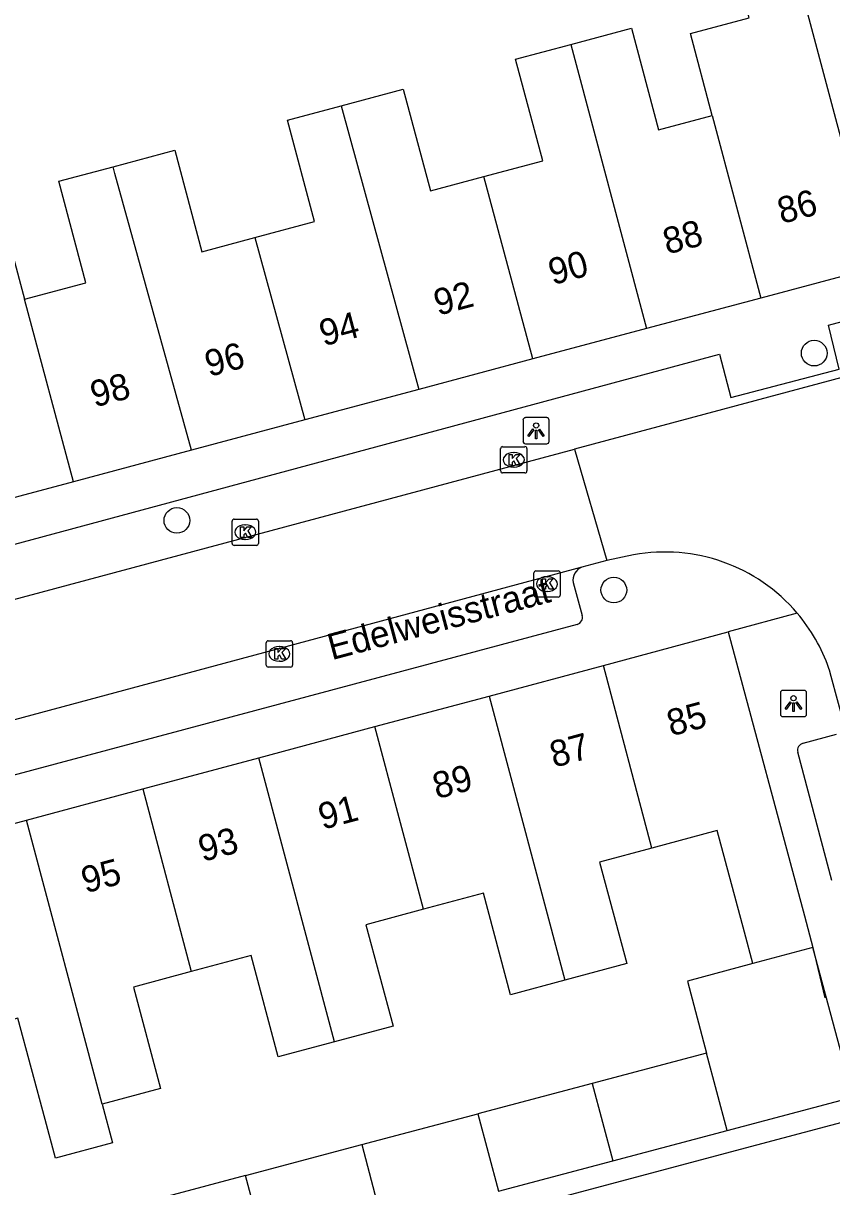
# Model space of a CAD drawing. Extents: x 162542 to 163144, y 380786 to 381511.
# Drawn here: x 162830.58 to 162861.37, y 381053.03 to 381097.35 of the extents above; entities that cross this region are included whole.
import ezdxf

# ---------------------------------------------------------------- set-up
doc = ezdxf.new("R2010")
doc.units = 0
for name, color, linetype in [('IMGEO_Boom', 7, 'Continuous'), ('IMGEO_Kolk', 7, 'Continuous'), ('IMGEO_Lichtpunt', 7, 'Continuous'), ('IMGEO_Muur', 7, 'Continuous'), ('IMGEO_Openbare_ruimte_label', 7, 'Continuous'), ('IMGEO_Pand', 7, 'Continuous'), ('IMGEO_Pand_nummerreeks', 7, 'Continuous'), ('IMGEO_Rijbaan_lokaal_open', 7, 'Continuous'), ('IMGEO_Voetpad_open', 7, 'Continuous')]:
    doc.layers.add(name, color=color, linetype=linetype)

msp = doc.modelspace()

# ---------------------------------------------------------------- linework, layer by layer
at = {"layer": 'IMGEO_Boom'}
for centre in [(162860.706, 381084.784), (162836.43, 381078.412), (162853.074, 381075.759)]:
    msp.add_circle(centre, 0.489, dxfattribs=at)
at = {"layer": 'IMGEO_Kolk'}
for p, q in [((162848.763, 381080.295), (162848.763, 381081.147)), ((162848.838, 381081.221), (162849.69, 381081.221)), ((162849.764, 381081.147), (162849.764, 381080.295)), ((162849.251, 381081.001), (162849.276, 381081.001)), ((162849.69, 381080.221), (162848.838, 381080.221)), ((162849.274, 381080.441), (162849.249, 381080.441)), ((162838.609, 381078.462), (162839.461, 381078.462)), ((162838.534, 381077.536), (162838.534, 381078.388)), ((162839.022, 381078.242), (162839.047, 381078.242)), ((162839.535, 381078.388), (162839.535, 381077.536)), ((162839.045, 381077.682), (162839.02, 381077.682)), ((162839.461, 381077.462), (162838.609, 381077.462)), ((162850.031, 381075.563), (162850.031, 381076.415)), ((162850.106, 381076.489), (162850.958, 381076.489)), ((162850.519, 381076.269), (162850.544, 381076.269)), ((162851.032, 381076.415), (162851.032, 381075.563)), ((162850.958, 381075.489), (162850.106, 381075.489)), ((162850.542, 381075.709), (162850.517, 381075.709)), ((162839.836, 381072.901), (162839.836, 381073.753)), ((162839.911, 381073.827), (162840.763, 381073.827)), ((162840.324, 381073.607), (162840.349, 381073.607)), ((162840.837, 381073.753), (162840.837, 381072.901)), ((162840.763, 381072.827), (162839.911, 381072.827)), ((162840.347, 381073.047), (162840.322, 381073.047))]:
    msp.add_line(p, q, dxfattribs=at)
for points in [[(162848.763, 381080.295), (162848.763, 381081.147)], [(162848.838, 381081.221), (162849.69, 381081.221)], [(162849.764, 381081.147), (162849.764, 381080.295)], [(162849.084, 381080.921), (162849.207, 381080.921), (162849.207, 381080.77), (162849.337, 381080.921), (162849.501, 381080.921), (162849.355, 381080.77), (162849.508, 381080.521), (162849.356, 381080.521), (162849.271, 381080.685), (162849.207, 381080.618), (162849.207, 381080.521), (162849.084, 381080.521), (162849.084, 381080.921)], [(162849.69, 381080.221), (162848.838, 381080.221)], [(162838.609, 381078.462), (162839.461, 381078.462)], [(162838.534, 381077.536), (162838.534, 381078.388)], [(162838.855, 381078.162), (162838.978, 381078.162), (162838.978, 381078.011), (162839.108, 381078.162), (162839.272, 381078.162), (162839.126, 381078.011), (162839.279, 381077.762), (162839.127, 381077.762), (162839.042, 381077.926), (162838.978, 381077.859), (162838.978, 381077.762), (162838.855, 381077.762), (162838.855, 381078.162)], [(162839.535, 381078.388), (162839.535, 381077.536)], [(162839.461, 381077.462), (162838.609, 381077.462)], [(162850.031, 381075.563), (162850.031, 381076.415)], [(162850.106, 381076.489), (162850.958, 381076.489)], [(162850.352, 381076.189), (162850.475, 381076.189), (162850.475, 381076.038), (162850.605, 381076.189), (162850.769, 381076.189), (162850.623, 381076.038), (162850.776, 381075.789), (162850.624, 381075.789), (162850.539, 381075.953), (162850.475, 381075.886), (162850.475, 381075.789), (162850.352, 381075.789), (162850.352, 381076.189)], [(162851.032, 381076.415), (162851.032, 381075.563)], [(162850.958, 381075.489), (162850.106, 381075.489)], [(162839.836, 381072.901), (162839.836, 381073.753)], [(162839.911, 381073.827), (162840.763, 381073.827)], [(162840.157, 381073.527), (162840.28, 381073.527), (162840.28, 381073.376), (162840.41, 381073.527), (162840.574, 381073.527), (162840.428, 381073.376), (162840.581, 381073.127), (162840.429, 381073.127), (162840.344, 381073.291), (162840.28, 381073.224), (162840.28, 381073.127), (162840.157, 381073.127), (162840.157, 381073.527)], [(162840.837, 381073.753), (162840.837, 381072.901)], [(162840.763, 381072.827), (162839.911, 381072.827)]]:
    msp.add_lwpolyline(points, dxfattribs=at)
for centre, start, end in [((162848.84, 381081.145), 91.552, 178.448), ((162848.84, 381081.145), 91.552, 178.448), ((162849.688, 381081.145), 1.552, 88.448), ((162849.688, 381081.145), 1.552, 88.448), ((162848.84, 381080.297), 181.552, 268.448), ((162848.84, 381080.297), 181.552, 268.448), ((162849.688, 381080.297), 271.552, 358.448), ((162849.688, 381080.297), 271.552, 358.448), ((162838.611, 381078.386), 91.552, 178.448), ((162838.611, 381078.386), 91.552, 178.448), ((162839.459, 381078.386), 1.552, 88.448), ((162839.459, 381078.386), 1.552, 88.448), ((162838.611, 381077.538), 181.552, 268.448), ((162838.611, 381077.538), 181.552, 268.448), ((162839.459, 381077.538), 271.552, 358.448), ((162839.459, 381077.538), 271.552, 358.448), ((162850.108, 381076.413), 91.552, 178.448), ((162850.108, 381076.413), 91.552, 178.448), ((162850.956, 381076.413), 1.552, 88.448), ((162850.956, 381076.413), 1.552, 88.448), ((162850.108, 381075.565), 181.552, 268.448), ((162850.108, 381075.565), 181.552, 268.448), ((162850.956, 381075.565), 271.552, 358.448), ((162850.956, 381075.565), 271.552, 358.448), ((162839.913, 381073.751), 91.552, 178.448), ((162839.913, 381073.751), 91.552, 178.448), ((162840.761, 381073.751), 1.552, 88.448), ((162840.761, 381073.751), 1.552, 88.448), ((162839.913, 381072.903), 181.552, 268.448), ((162839.913, 381072.903), 181.552, 268.448), ((162840.761, 381072.903), 271.552, 358.448), ((162840.761, 381072.903), 271.552, 358.448)]:
    msp.add_arc(centre, 0.0765, start, end, dxfattribs=at)
for centre, major_axis, ratio, start_param, end_param in [((162849.25, 381080.721), (-0.387, 0.002), 0.722429, 4.712389, 7.853982), ((162849.275, 381080.721), (-0.39, 0.002), 0.717154, 1.570796, 4.712389), ((162839.021, 381077.962), (-0.387, 0.002), 0.722429, 4.712389, 7.853982), ((162839.046, 381077.962), (-0.39, 0.002), 0.717154, 1.570796, 4.712389), ((162850.518, 381075.989), (-0.387, 0.002), 0.722429, 4.712389, 7.853982), ((162850.543, 381075.989), (-0.39, 0.002), 0.717154, 1.570796, 4.712389), ((162840.323, 381073.327), (-0.387, 0.002), 0.722429, 4.712389, 7.853982), ((162840.348, 381073.327), (-0.39, 0.002), 0.717154, 1.570796, 4.712389)]:
    msp.add_ellipse(centre, major_axis=major_axis, ratio=ratio, start_param=start_param, end_param=end_param, dxfattribs=at)
at = {"layer": 'IMGEO_Lichtpunt'}
for p, q in [((162849.614, 381082.231), (162849.614, 381081.424)), ((162849.614, 381082.231), (162849.614, 381081.424)), ((162850.516, 381082.326), (162849.708, 381082.326)), ((162850.516, 381082.326), (162849.708, 381082.326)), ((162850.61, 381081.424), (162850.61, 381082.231)), ((162850.61, 381081.424), (162850.61, 381082.231)), ((162849.708, 381081.33), (162850.516, 381081.33)), ((162849.708, 381081.33), (162850.516, 381081.33)), ((162859.419, 381071.841), (162859.419, 381071.034)), ((162859.419, 381071.841), (162859.419, 381071.034)), ((162860.321, 381071.936), (162859.513, 381071.936)), ((162860.321, 381071.936), (162859.513, 381071.936)), ((162860.415, 381071.034), (162860.415, 381071.841)), ((162860.415, 381071.034), (162860.415, 381071.841)), ((162859.513, 381070.94), (162860.321, 381070.94)), ((162859.513, 381070.94), (162860.321, 381070.94))]:
    msp.add_line(p, q, dxfattribs=at)
for points in [[(162849.988, 381081.895), (162850.027, 381081.867), (162849.839, 381081.605), (162849.801, 381081.632), (162849.988, 381081.895)], [(162850.09, 381081.847), (162850.137, 381081.847), (162850.137, 381081.525), (162850.09, 381081.525), (162850.09, 381081.847)], [(162850.2, 381081.867), (162850.238, 381081.894), (162850.425, 381081.632), (162850.386, 381081.604), (162850.2, 381081.867)], [(162859.793, 381071.505), (162859.832, 381071.477), (162859.644, 381071.215), (162859.606, 381071.242), (162859.793, 381071.505)], [(162859.895, 381071.457), (162859.942, 381071.457), (162859.942, 381071.135), (162859.895, 381071.135), (162859.895, 381071.457)], [(162860.005, 381071.477), (162860.043, 381071.504), (162860.23, 381071.242), (162860.191, 381071.214), (162860.005, 381071.477)]]:
    msp.add_lwpolyline(points, dxfattribs=at)
for centre in [(162850.113, 381082.029), (162859.918, 381071.639)]:
    msp.add_circle(centre, 0.0994, dxfattribs=at)
for centre, start, end in [((162849.708, 381082.231), 90, 180), ((162849.708, 381082.231), 90, 180), ((162850.516, 381082.231), 0, 90), ((162850.516, 381082.231), 0, 90), ((162849.708, 381081.424), 180, 270), ((162849.708, 381081.424), 180, 270), ((162850.516, 381081.424), 270, 0), ((162850.516, 381081.424), 270, 360), ((162859.513, 381071.841), 90, 180), ((162859.513, 381071.841), 90, 180), ((162860.321, 381071.841), 0, 90), ((162860.321, 381071.841), 0, 90), ((162859.513, 381071.034), 180, 270), ((162859.513, 381071.034), 180, 270), ((162860.321, 381071.034), 270, 0), ((162860.321, 381071.034), 270, 360)]:
    msp.add_arc(centre, 0.0946, start, end, dxfattribs=at)
at = {"layer": 'IMGEO_Muur'}
msp.add_lwpolyline([(162860.655, 381062.149), (162861.114, 381060.224)], dxfattribs=at)
at = {"layer": 'IMGEO_Pand'}
for points in [[(162856.825, 381093.84), (162855.994, 381096.96), (162858.228, 381097.555), (162858.029, 381098.301), (162857.181, 381101.483), (162859.313, 381102.051), (162860.16, 381098.87)], [(162863.043, 381088.048), (162860.16, 381098.87)], [(162851.43, 381096.539), (162853.749, 381097.158), (162854.781, 381093.294), (162856.825, 381093.84)], [(162848.125, 381091.517), (162850.366, 381092.115), (162849.334, 381095.979), (162851.43, 381096.539)], [(162851.43, 381096.539), (162854.314, 381085.717)], [(162842.688, 381094.204), (162845.054, 381094.836), (162846.086, 381090.972), (162848.125, 381091.517)], [(162839.404, 381089.187), (162841.67, 381089.793), (162840.638, 381093.657), (162842.688, 381094.204)], [(162842.688, 381094.204), (162845.647, 381083.402)], [(162856.825, 381093.84), (162858.678, 381086.882)], [(162833.997, 381091.883), (162836.349, 381092.511), (162837.381, 381088.647), (162839.404, 381089.187)], [(162830.63, 381086.845), (162832.965, 381087.468), (162831.933, 381091.332), (162833.997, 381091.883)], [(162836.981, 381081.088), (162834.067, 381091.626), (162833.997, 381091.883)], [(162849.985, 381084.561), (162848.125, 381091.517)], [(162825.305, 381089.562), (162827.605, 381090.177), (162827.746, 381089.648), (162829.739, 381090.18), (162830.63, 381086.845)], [(162839.404, 381089.187), (162841.304, 381082.242)], [(162863.043, 381088.048), (162858.678, 381086.882)], [(162832.488, 381079.888), (162830.63, 381086.845)], [(162858.678, 381086.882), (162854.314, 381085.717)], [(162854.314, 381085.717), (162849.985, 381084.561)], [(162849.985, 381084.561), (162845.647, 381083.402)], [(162845.647, 381083.402), (162841.304, 381082.242)], [(162841.304, 381082.242), (162836.981, 381081.088)], [(162836.981, 381081.088), (162832.488, 381079.888)], [(162832.488, 381079.888), (162828.195, 381078.741)], [(162852.675, 381072.888), (162857.433, 381074.164)], [(162857.433, 381074.164), (162860.334, 381063.346), (162860.655, 381062.149)], [(162848.329, 381071.723), (162852.675, 381072.888)], [(162854.525, 381065.93), (162852.675, 381072.888)], [(162843.975, 381070.556), (162848.329, 381071.723)], [(162848.329, 381071.723), (162851.206, 381060.899)], [(162839.552, 381069.37), (162843.975, 381070.556)], [(162845.825, 381063.598), (162843.975, 381070.556)], [(162835.13, 381068.184), (162839.552, 381069.37)], [(162842.43, 381058.546), (162839.552, 381069.37)], [(162830.706, 381066.998), (162835.13, 381068.184)], [(162835.13, 381068.184), (162836.98, 381061.226)], [(162826.284, 381065.812), (162830.706, 381066.998)], [(162833.584, 381056.174), (162830.706, 381066.998)], [(162858.366, 381061.535), (162858.045, 381062.733), (162857.01, 381066.597), (162854.525, 381065.93)], [(162854.525, 381065.93), (162852.529, 381065.395), (162853.564, 381061.531), (162851.206, 381060.899)], [(162851.206, 381060.899), (162849.14, 381060.345), (162848.105, 381064.209), (162845.825, 381063.598)], [(162845.825, 381063.598), (162843.633, 381063.01), (162844.668, 381059.146), (162842.43, 381058.546)], [(162860.655, 381062.149), (162858.366, 381061.535)], [(162862.122, 381056.428), (162862.19, 381056.446), (162860.655, 381062.149)], [(162842.43, 381058.546), (162840.292, 381057.973), (162839.257, 381061.837), (162836.98, 381061.226)], [(162836.98, 381061.226), (162834.776, 381060.635), (162835.811, 381056.771), (162833.584, 381056.174)], [(162858.366, 381061.535), (162855.874, 381060.867), (162855.939, 381060.623), (162856.603, 381058.12)], [(162833.584, 381056.174), (162833.975, 381054.702), (162831.8, 381054.119), (162831.406, 381055.59), (162830.371, 381059.454), (162828.134, 381058.854)], [(162856.603, 381058.12), (162852.252, 381056.964)], [(162857.386, 381055.171), (162856.603, 381058.12)], [(162852.252, 381056.964), (162847.896, 381055.808)], [(162852.252, 381056.964), (162853.036, 381054.015)], [(162857.386, 381055.171), (162862.122, 381056.428)], [(162843.47, 381054.633), (162847.896, 381055.808)], [(162847.896, 381055.808), (162848.68, 381052.859)], [(162862.332, 381055.632), (162857.502, 381054.343), (162851.459, 381052.73), (162849.79, 381052.284)], [(162853.036, 381054.015), (162857.386, 381055.171)], [(162839.045, 381053.458), (162843.47, 381054.633)], [(162843.47, 381054.633), (162844.255, 381051.684)], [(162848.68, 381052.859), (162853.036, 381054.015)], [(162839.045, 381053.458), (162834.619, 381052.282)], [(162839.83, 381050.509), (162839.045, 381053.458)]]:
    msp.add_lwpolyline(points, dxfattribs=at)
at = {"layer": 'IMGEO_Rijbaan_lokaal_open'}
for points in [[(162868.302, 381085.609), (162851.581, 381081.128)], [(162813.721, 381070.983), (162851.581, 381081.128)], [(162851.581, 381081.128), (162852.809, 381076.882)], [(162853.828, 381077.1), (162852.809, 381076.882)], [(162851.855, 381076.637), (162815.604, 381066.881)], [(162852.809, 381076.882), (162851.855, 381076.637)], [(162861.83, 381070.69), (162861.348, 381072.461), (162861.286, 381072.703), (162861.266, 381072.777)]]:
    msp.add_lwpolyline(points, dxfattribs=at)
for centre, radius, start, end in [((162855.024, 381070.597), 6.612, 40.4174, 100.4219), ((162855.031, 381070.602), 6.603, 19.2296, 40.424)]:
    msp.add_arc(centre, radius, start, end, dxfattribs=at)
at = {"layer": 'IMGEO_Voetpad_open'}
for points in [[(162829.44, 381077.293), (162857.097, 381084.74), (162857.529, 381083.089), (162861.656, 381084.179), (162861.251, 381085.851), (162866.655, 381087.296), (162874.876, 381089.481), (162907.148, 381098.095), (162922.391, 381102.163), (162922.875, 381100.201)], [(162851.524, 381076.045), (162851.873, 381074.788)], [(162860.058, 381074.884), (162857.433, 381074.164)], [(162851.679, 381074.446), (162816.78, 381065.113)], [(162860.287, 381069.926), (162861.55, 381070.276)], [(162861.374, 381064.691), (162860.077, 381069.583)]]:
    msp.add_lwpolyline(points, dxfattribs=at)
for centre, radius, start, end in [((162852.077, 381076.124), 0.559, 113.4411, 188.1379), ((162851.578, 381074.73), 0.301, 289.674, 11.1977), ((162860.355, 381069.649), 0.286, 103.7503, 193.296)]:
    msp.add_arc(centre, radius, start, end, dxfattribs=at)

# ---------------------------------------------------------------- texts
at = {"layer": 'IMGEO_Openbare_ruimte_label'}
msp.add_text('Edelweisstraat', height=1, rotation=14.8982, dxfattribs=at).set_placement((162842.329, 381073.084))
at = {"layer": 'IMGEO_Pand_nummerreeks'}
for s, rotation, p in [('86', 14.9542, (162859.463, 381089.701)), ('88', 14.9536, (162855.103, 381088.536)), ('90', 14.9536, (162850.741, 381087.371)), ('92', 14.9536, (162846.373, 381086.204)), ('94', 14.9536, (162842.014, 381085.039)), ('96', 14.9536, (162837.652, 381083.874)), ('98', 14.9536, (162833.292, 381082.71)), ('85', 15.0096, (162855.253, 381070.184)), ('87', 15.0096, (162850.792, 381068.988)), ('89', 15.0096, (162846.331, 381067.791)), ('91', 15.0096, (162841.978, 381066.624)), ('93', 15.0096, (162837.408, 381065.399)), ('95', 15.0096, (162832.947, 381064.203))]:
    msp.add_text(s, height=1, rotation=rotation, dxfattribs=at).set_placement(p)

doc.saveas('drawing.dxf')
